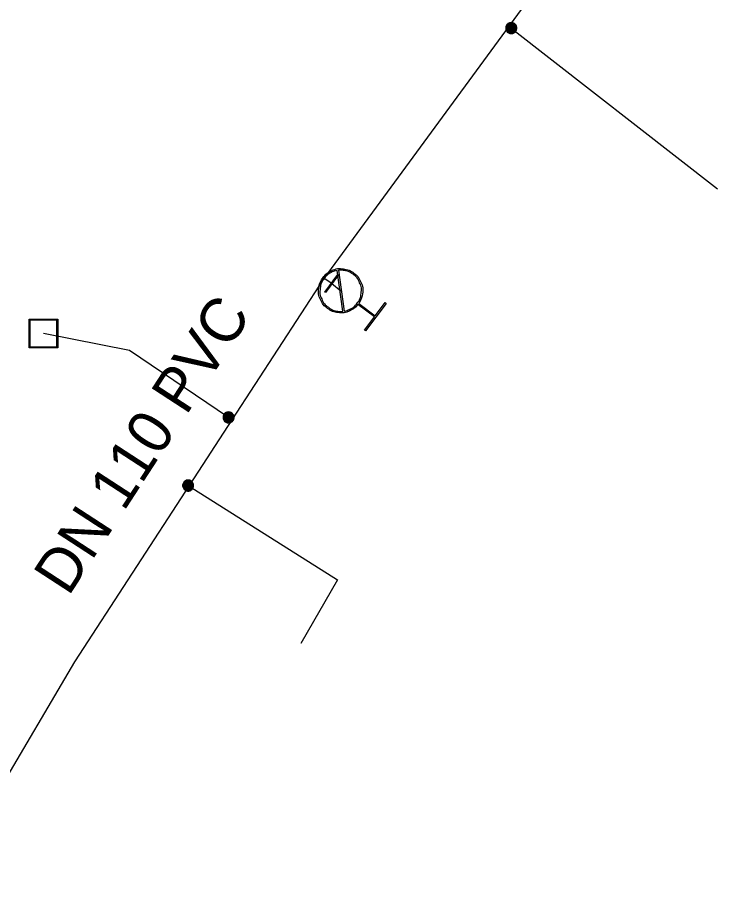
# Model space of a CAD drawing. Extents: x -832382 to -831581, y -1074670 to -1074251.
# Drawn here: x -831800.46 to -831768.62, y -1074542.98 to -1074502.92 of the extents above; entities that cross this region are included whole.
import ezdxf

# ---------------------------------------------------------------- set-up
doc = ezdxf.new("R2010")
doc.units = 0
for name, color, linetype in [('Hyd-odbočka', 7, 'Continuous'), ('Hyd-šoupě', 7, 'Continuous'), ('Hydrant', 7, 'Continuous'), ('Přípojka vodovodu', 7, 'Continuous'), ('Přípojkový uzávěr', 7, 'Continuous'), ('Roz-řad', 7, 'Continuous'), ('Roz-řad-popis základní', 7, 'Continuous'), ('Šachta vodovodní', 7, 'Continuous')]:
    doc.layers.add(name, color=color, linetype=linetype)

msp = doc.modelspace()

# ---------------------------------------------------------------- linework, layer by layer
at = {"layer": 'Hyd-odbočka'}
for q in [(-831786.517, -1074514.779), (-831785.76, -1074515.34)]:
    msp.add_line((-831786.17, -1074515.01), q, dxfattribs=at)
at = {"layer": 'Hyd-šoupě'}
msp.add_lwpolyline([(-831786.479, -1074515.403), (-831785.885, -1074514.599), (-831785.86, -1074514.617), (-831786.454, -1074515.421), (-831786.479, -1074515.403)], dxfattribs=at)
at = {"layer": 'Hydrant'}
for points in [[(-831785.656, -1074516.274), (-831785.926, -1074514.414)], [(-831785.864, -1074514.406), (-831785.596, -1074516.265)], [(-831784.94, -1074515.914), (-831784.189, -1074516.475), (-831783.74, -1074515.874), (-831783.69, -1074515.912), (-831784.626, -1074517.163), (-831784.676, -1074517.126), (-831784.227, -1074516.525), (-831784.978, -1074515.964)]]:
    msp.add_lwpolyline(points, dxfattribs=at)
for points in [[(-831784.978, -1074515.964), (-831785.126, -1074516.148), (-831785.357, -1074516.256), (-831785.603, -1074516.369), (-831785.876, -1074516.334), (-831786.149, -1074516.298), (-831786.359, -1074516.141), (-831786.567, -1074515.985), (-831786.679, -1074515.737), (-831786.791, -1074515.489), (-831786.754, -1074515.219), (-831786.716, -1074514.949), (-831786.561, -1074514.741), (-831786.405, -1074514.533), (-831786.157, -1074514.421), (-831785.909, -1074514.309), (-831785.639, -1074514.346), (-831785.369, -1074514.384), (-831785.161, -1074514.539), (-831784.952, -1074514.696), (-831784.84, -1074514.948), (-831784.728, -1074515.199), (-831784.768, -1074515.467), (-831784.804, -1074515.718), (-831784.94, -1074515.914)], [(-831785.926, -1074514.414), (-831786.031, -1074514.433), (-831786.131, -1074514.48), (-831786.365, -1074514.583), (-831786.511, -1074514.779), (-831786.657, -1074514.974), (-831786.692, -1074515.228), (-831786.726, -1074515.481), (-831786.622, -1074515.713), (-831786.517, -1074515.945), (-831786.321, -1074516.091), (-831786.124, -1074516.238), (-831785.868, -1074516.271), (-831785.759, -1074516.285), (-831785.656, -1074516.274)], [(-831785.596, -1074516.265), (-831785.486, -1074516.245), (-831785.382, -1074516.198), (-831785.151, -1074516.091), (-831785.009, -1074515.901), (-831784.868, -1074515.712), (-831784.83, -1074515.46), (-831784.793, -1074515.207), (-831784.897, -1074514.972), (-831785.002, -1074514.736), (-831785.199, -1074514.589), (-831785.394, -1074514.443), (-831785.647, -1074514.41), (-831785.757, -1074514.394), (-831785.864, -1074514.406)]]:
    msp.add_open_spline(points, degree=3, dxfattribs=at)
at = {"layer": 'Přípojka vodovodu'}
for points in [[(-831778.085, -1074503.291), (-831778, -1074503.39), (-831768.624, -1074510.708)], [(-831790.697, -1074521.21), (-831790.86, -1074521.1), (-831795.371, -1074518.06), (-831799.285, -1074517.283)], [(-831792.611, -1074524.153), (-831792.7, -1074524.2), (-831785.906, -1074528.481), (-831787.57, -1074531.385)]]:
    msp.add_lwpolyline(points, dxfattribs=at)
at = {"layer": 'Přípojkový uzávěr'}
for points in [[(-831778, -1074503.14), (-831777.937, -1074503.14), (-831777.877, -1074503.172), (-831777.818, -1074503.204), (-831777.784, -1074503.265), (-831777.75, -1074503.325), (-831777.75, -1074503.39), (-831777.75, -1074503.455), (-831777.783, -1074503.515), (-831777.816, -1074503.574), (-831777.875, -1074503.607), (-831777.935, -1074503.64), (-831778, -1074503.64), (-831778.065, -1074503.64), (-831778.125, -1074503.607), (-831778.184, -1074503.574), (-831778.217, -1074503.515), (-831778.25, -1074503.455), (-831778.25, -1074503.39), (-831778.25, -1074503.325), (-831778.216, -1074503.265), (-831778.183, -1074503.204), (-831778.123, -1074503.172), (-831778.063, -1074503.14), (-831778, -1074503.14)], [(-831778, -1074503.163), (-831778.057, -1074503.163), (-831778.112, -1074503.193), (-831778.166, -1074503.222), (-831778.196, -1074503.276), (-831778.227, -1074503.331), (-831778.227, -1074503.39), (-831778.227, -1074503.449), (-831778.197, -1074503.503), (-831778.167, -1074503.557), (-831778.113, -1074503.587), (-831778.059, -1074503.617), (-831778, -1074503.617), (-831777.941, -1074503.617), (-831777.887, -1074503.587), (-831777.833, -1074503.557), (-831777.803, -1074503.503), (-831777.773, -1074503.449), (-831777.773, -1074503.39), (-831777.773, -1074503.331), (-831777.804, -1074503.276), (-831777.835, -1074503.222), (-831777.889, -1074503.193), (-831777.943, -1074503.163), (-831778, -1074503.163)], [(-831778, -1074503.181), (-831777.947, -1074503.181), (-831777.897, -1074503.208), (-831777.847, -1074503.234), (-831777.819, -1074503.285), (-831777.791, -1074503.335), (-831777.791, -1074503.39), (-831777.791, -1074503.445), (-831777.818, -1074503.494), (-831777.845, -1074503.544), (-831777.896, -1074503.572), (-831777.946, -1074503.599), (-831778, -1074503.599), (-831778.054, -1074503.599), (-831778.104, -1074503.572), (-831778.155, -1074503.544), (-831778.182, -1074503.494), (-831778.209, -1074503.445), (-831778.209, -1074503.39), (-831778.209, -1074503.335), (-831778.181, -1074503.285), (-831778.153, -1074503.234), (-831778.103, -1074503.208), (-831778.053, -1074503.181), (-831778, -1074503.181)], [(-831778, -1074503.203), (-831778.079, -1074503.203), (-831778.133, -1074503.257), (-831778.188, -1074503.312), (-831778.188, -1074503.39), (-831778.188, -1074503.468), (-831778.133, -1074503.523), (-831778.078, -1074503.578), (-831778, -1074503.578), (-831777.922, -1074503.578), (-831777.867, -1074503.523), (-831777.812, -1074503.468), (-831777.812, -1074503.39), (-831777.812, -1074503.312), (-831777.867, -1074503.257), (-831777.922, -1074503.203), (-831778, -1074503.203)], [(-831778, -1074503.225), (-831777.932, -1074503.225), (-831777.884, -1074503.273), (-831777.836, -1074503.321), (-831777.836, -1074503.39), (-831777.836, -1074503.458), (-831777.884, -1074503.506), (-831777.932, -1074503.554), (-831778, -1074503.554), (-831778.069, -1074503.554), (-831778.117, -1074503.506), (-831778.165, -1074503.458), (-831778.165, -1074503.39), (-831778.165, -1074503.321), (-831778.117, -1074503.273), (-831778.069, -1074503.225), (-831778, -1074503.225)], [(-831778, -1074503.245), (-831778.061, -1074503.245), (-831778.103, -1074503.287), (-831778.145, -1074503.33), (-831778.145, -1074503.39), (-831778.145, -1074503.449), (-831778.103, -1074503.492), (-831778.061, -1074503.534), (-831778, -1074503.534), (-831777.941, -1074503.534), (-831777.898, -1074503.492), (-831777.856, -1074503.449), (-831777.856, -1074503.39), (-831777.856, -1074503.33), (-831777.898, -1074503.287), (-831777.94, -1074503.245), (-831778, -1074503.245)], [(-831778, -1074503.265), (-831777.948, -1074503.265), (-831777.911, -1074503.302), (-831777.875, -1074503.338), (-831777.875, -1074503.39), (-831777.875, -1074503.442), (-831777.912, -1074503.479), (-831777.948, -1074503.515), (-831778, -1074503.515), (-831778.052, -1074503.515), (-831778.088, -1074503.479), (-831778.125, -1074503.442), (-831778.125, -1074503.39), (-831778.125, -1074503.338), (-831778.089, -1074503.302), (-831778.052, -1074503.265), (-831778, -1074503.265)], [(-831778, -1074503.288), (-831778.042, -1074503.288), (-831778.072, -1074503.318), (-831778.102, -1074503.348), (-831778.102, -1074503.39), (-831778.102, -1074503.432), (-831778.072, -1074503.462), (-831778.042, -1074503.491), (-831778, -1074503.491), (-831777.958, -1074503.491), (-831777.928, -1074503.462), (-831777.899, -1074503.432), (-831777.899, -1074503.39), (-831777.899, -1074503.348), (-831777.928, -1074503.318), (-831777.958, -1074503.288), (-831778, -1074503.288)], [(-831778, -1074503.306), (-831777.965, -1074503.306), (-831777.941, -1074503.33), (-831777.916, -1074503.355), (-831777.916, -1074503.39), (-831777.916, -1074503.425), (-831777.941, -1074503.449), (-831777.965, -1074503.474), (-831778, -1074503.474), (-831778.035, -1074503.474), (-831778.06, -1074503.449), (-831778.084, -1074503.425), (-831778.084, -1074503.39), (-831778.084, -1074503.355), (-831778.06, -1074503.33), (-831778.035, -1074503.306), (-831778, -1074503.306)], [(-831778, -1074503.328), (-831778.026, -1074503.328), (-831778.044, -1074503.346), (-831778.062, -1074503.364), (-831778.062, -1074503.39), (-831778.062, -1074503.416), (-831778.044, -1074503.434), (-831778.026, -1074503.453), (-831778, -1074503.453), (-831777.974, -1074503.453), (-831777.956, -1074503.434), (-831777.938, -1074503.416), (-831777.938, -1074503.39), (-831777.938, -1074503.364), (-831777.956, -1074503.346), (-831777.974, -1074503.328), (-831778, -1074503.328)], [(-831778, -1074503.351), (-831777.984, -1074503.351), (-831777.972, -1074503.362), (-831777.961, -1074503.373), (-831777.961, -1074503.39), (-831777.961, -1074503.406), (-831777.972, -1074503.418), (-831777.984, -1074503.429), (-831778, -1074503.429), (-831778.016, -1074503.429), (-831778.028, -1074503.418), (-831778.039, -1074503.406), (-831778.039, -1074503.39), (-831778.039, -1074503.373), (-831778.028, -1074503.362), (-831778.016, -1074503.351), (-831778, -1074503.351)], [(-831778, -1074503.367), (-831778.01, -1074503.367), (-831778.017, -1074503.373), (-831778.024, -1074503.38), (-831778.024, -1074503.39), (-831778.024, -1074503.4), (-831778.017, -1074503.407), (-831778.01, -1074503.413), (-831778, -1074503.413), (-831777.99, -1074503.413), (-831777.984, -1074503.407), (-831777.977, -1074503.4), (-831777.977, -1074503.39), (-831777.977, -1074503.38), (-831777.984, -1074503.373), (-831777.99, -1074503.367), (-831778, -1074503.367)], [(-831790.86, -1074520.85), (-831790.797, -1074520.85), (-831790.737, -1074520.882), (-831790.678, -1074520.914), (-831790.644, -1074520.975), (-831790.61, -1074521.035), (-831790.61, -1074521.1), (-831790.61, -1074521.165), (-831790.643, -1074521.225), (-831790.676, -1074521.284), (-831790.735, -1074521.317), (-831790.795, -1074521.35), (-831790.86, -1074521.35), (-831790.925, -1074521.35), (-831790.985, -1074521.317), (-831791.044, -1074521.284), (-831791.077, -1074521.225), (-831791.11, -1074521.165), (-831791.11, -1074521.1), (-831791.11, -1074521.035), (-831791.076, -1074520.975), (-831791.043, -1074520.914), (-831790.983, -1074520.882), (-831790.923, -1074520.85), (-831790.86, -1074520.85)], [(-831790.86, -1074520.873), (-831790.917, -1074520.873), (-831790.972, -1074520.903), (-831791.026, -1074520.932), (-831791.056, -1074520.986), (-831791.087, -1074521.041), (-831791.087, -1074521.1), (-831791.087, -1074521.159), (-831791.057, -1074521.213), (-831791.027, -1074521.267), (-831790.973, -1074521.297), (-831790.919, -1074521.327), (-831790.86, -1074521.327), (-831790.801, -1074521.327), (-831790.747, -1074521.297), (-831790.693, -1074521.267), (-831790.663, -1074521.213), (-831790.633, -1074521.159), (-831790.633, -1074521.1), (-831790.633, -1074521.041), (-831790.664, -1074520.986), (-831790.695, -1074520.932), (-831790.749, -1074520.903), (-831790.803, -1074520.873), (-831790.86, -1074520.873)], [(-831790.86, -1074520.891), (-831790.807, -1074520.891), (-831790.757, -1074520.918), (-831790.707, -1074520.944), (-831790.679, -1074520.995), (-831790.651, -1074521.045), (-831790.651, -1074521.1), (-831790.651, -1074521.155), (-831790.678, -1074521.204), (-831790.705, -1074521.254), (-831790.756, -1074521.282), (-831790.806, -1074521.309), (-831790.86, -1074521.309), (-831790.914, -1074521.309), (-831790.964, -1074521.282), (-831791.015, -1074521.254), (-831791.042, -1074521.204), (-831791.069, -1074521.155), (-831791.069, -1074521.1), (-831791.069, -1074521.045), (-831791.041, -1074520.995), (-831791.013, -1074520.944), (-831790.963, -1074520.918), (-831790.913, -1074520.891), (-831790.86, -1074520.891)], [(-831790.86, -1074520.913), (-831790.939, -1074520.913), (-831790.993, -1074520.967), (-831791.047, -1074521.022), (-831791.047, -1074521.1), (-831791.047, -1074521.178), (-831790.993, -1074521.233), (-831790.938, -1074521.288), (-831790.86, -1074521.288), (-831790.782, -1074521.288), (-831790.727, -1074521.233), (-831790.672, -1074521.178), (-831790.672, -1074521.1), (-831790.672, -1074521.022), (-831790.727, -1074520.967), (-831790.782, -1074520.913), (-831790.86, -1074520.913)], [(-831790.86, -1074520.935), (-831790.792, -1074520.935), (-831790.744, -1074520.983), (-831790.696, -1074521.031), (-831790.696, -1074521.1), (-831790.696, -1074521.168), (-831790.744, -1074521.216), (-831790.792, -1074521.264), (-831790.86, -1074521.264), (-831790.929, -1074521.264), (-831790.977, -1074521.216), (-831791.025, -1074521.168), (-831791.025, -1074521.1), (-831791.025, -1074521.031), (-831790.977, -1074520.983), (-831790.929, -1074520.935), (-831790.86, -1074520.935)], [(-831790.86, -1074520.955), (-831790.921, -1074520.955), (-831790.963, -1074520.997), (-831791.005, -1074521.04), (-831791.005, -1074521.1), (-831791.005, -1074521.159), (-831790.963, -1074521.202), (-831790.921, -1074521.244), (-831790.86, -1074521.244), (-831790.801, -1074521.244), (-831790.758, -1074521.202), (-831790.716, -1074521.159), (-831790.716, -1074521.1), (-831790.716, -1074521.04), (-831790.758, -1074520.997), (-831790.8, -1074520.955), (-831790.86, -1074520.955)], [(-831790.86, -1074520.975), (-831790.808, -1074520.975), (-831790.771, -1074521.012), (-831790.735, -1074521.048), (-831790.735, -1074521.1), (-831790.735, -1074521.152), (-831790.772, -1074521.189), (-831790.808, -1074521.225), (-831790.86, -1074521.225), (-831790.912, -1074521.225), (-831790.948, -1074521.189), (-831790.985, -1074521.152), (-831790.985, -1074521.1), (-831790.985, -1074521.048), (-831790.949, -1074521.012), (-831790.912, -1074520.975), (-831790.86, -1074520.975)], [(-831790.86, -1074520.998), (-831790.902, -1074520.998), (-831790.932, -1074521.028), (-831790.962, -1074521.058), (-831790.962, -1074521.1), (-831790.962, -1074521.142), (-831790.932, -1074521.172), (-831790.902, -1074521.201), (-831790.86, -1074521.201), (-831790.818, -1074521.201), (-831790.788, -1074521.172), (-831790.759, -1074521.142), (-831790.759, -1074521.1), (-831790.759, -1074521.058), (-831790.788, -1074521.028), (-831790.818, -1074520.998), (-831790.86, -1074520.998)], [(-831790.86, -1074521.016), (-831790.825, -1074521.016), (-831790.801, -1074521.04), (-831790.776, -1074521.065), (-831790.776, -1074521.1), (-831790.776, -1074521.135), (-831790.801, -1074521.159), (-831790.825, -1074521.184), (-831790.86, -1074521.184), (-831790.895, -1074521.184), (-831790.92, -1074521.159), (-831790.944, -1074521.135), (-831790.944, -1074521.1), (-831790.944, -1074521.065), (-831790.92, -1074521.04), (-831790.895, -1074521.016), (-831790.86, -1074521.016)], [(-831790.86, -1074521.038), (-831790.886, -1074521.038), (-831790.904, -1074521.056), (-831790.922, -1074521.074), (-831790.922, -1074521.1), (-831790.922, -1074521.126), (-831790.904, -1074521.144), (-831790.886, -1074521.163), (-831790.86, -1074521.163), (-831790.834, -1074521.163), (-831790.816, -1074521.144), (-831790.797, -1074521.126), (-831790.797, -1074521.1), (-831790.797, -1074521.074), (-831790.816, -1074521.056), (-831790.834, -1074521.038), (-831790.86, -1074521.038)], [(-831790.86, -1074521.061), (-831790.844, -1074521.061), (-831790.832, -1074521.072), (-831790.821, -1074521.083), (-831790.821, -1074521.1), (-831790.821, -1074521.116), (-831790.832, -1074521.128), (-831790.844, -1074521.139), (-831790.86, -1074521.139), (-831790.876, -1074521.139), (-831790.888, -1074521.128), (-831790.899, -1074521.116), (-831790.899, -1074521.1), (-831790.899, -1074521.083), (-831790.888, -1074521.072), (-831790.876, -1074521.061), (-831790.86, -1074521.061)], [(-831790.86, -1074521.077), (-831790.87, -1074521.077), (-831790.877, -1074521.083), (-831790.884, -1074521.09), (-831790.884, -1074521.1), (-831790.884, -1074521.11), (-831790.877, -1074521.117), (-831790.87, -1074521.123), (-831790.86, -1074521.123), (-831790.85, -1074521.123), (-831790.844, -1074521.117), (-831790.837, -1074521.11), (-831790.837, -1074521.1), (-831790.837, -1074521.09), (-831790.844, -1074521.083), (-831790.85, -1074521.077), (-831790.86, -1074521.077)], [(-831792.7, -1074523.95), (-831792.637, -1074523.95), (-831792.577, -1074523.982), (-831792.518, -1074524.014), (-831792.484, -1074524.075), (-831792.45, -1074524.135), (-831792.45, -1074524.2), (-831792.45, -1074524.265), (-831792.483, -1074524.325), (-831792.516, -1074524.384), (-831792.575, -1074524.417), (-831792.635, -1074524.45), (-831792.7, -1074524.45), (-831792.765, -1074524.45), (-831792.825, -1074524.417), (-831792.884, -1074524.384), (-831792.917, -1074524.325), (-831792.95, -1074524.265), (-831792.95, -1074524.2), (-831792.95, -1074524.135), (-831792.916, -1074524.075), (-831792.883, -1074524.014), (-831792.823, -1074523.982), (-831792.763, -1074523.95), (-831792.7, -1074523.95)], [(-831792.7, -1074523.973), (-831792.757, -1074523.973), (-831792.812, -1074524.003), (-831792.866, -1074524.032), (-831792.896, -1074524.086), (-831792.927, -1074524.141), (-831792.927, -1074524.2), (-831792.927, -1074524.259), (-831792.897, -1074524.313), (-831792.867, -1074524.367), (-831792.813, -1074524.397), (-831792.759, -1074524.427), (-831792.7, -1074524.427), (-831792.641, -1074524.427), (-831792.587, -1074524.397), (-831792.533, -1074524.367), (-831792.503, -1074524.313), (-831792.473, -1074524.259), (-831792.473, -1074524.2), (-831792.473, -1074524.141), (-831792.504, -1074524.086), (-831792.535, -1074524.032), (-831792.589, -1074524.003), (-831792.643, -1074523.973), (-831792.7, -1074523.973)], [(-831792.7, -1074523.991), (-831792.647, -1074523.991), (-831792.597, -1074524.018), (-831792.547, -1074524.044), (-831792.519, -1074524.095), (-831792.491, -1074524.145), (-831792.491, -1074524.2), (-831792.491, -1074524.255), (-831792.518, -1074524.304), (-831792.545, -1074524.354), (-831792.596, -1074524.382), (-831792.646, -1074524.409), (-831792.7, -1074524.409), (-831792.754, -1074524.409), (-831792.804, -1074524.382), (-831792.855, -1074524.354), (-831792.882, -1074524.304), (-831792.909, -1074524.255), (-831792.909, -1074524.2), (-831792.909, -1074524.145), (-831792.881, -1074524.095), (-831792.853, -1074524.044), (-831792.803, -1074524.018), (-831792.753, -1074523.991), (-831792.7, -1074523.991)], [(-831792.7, -1074524.012), (-831792.779, -1074524.012), (-831792.833, -1074524.067), (-831792.888, -1074524.122), (-831792.888, -1074524.2), (-831792.888, -1074524.278), (-831792.833, -1074524.333), (-831792.778, -1074524.387), (-831792.7, -1074524.387), (-831792.622, -1074524.387), (-831792.567, -1074524.333), (-831792.513, -1074524.278), (-831792.513, -1074524.2), (-831792.513, -1074524.122), (-831792.567, -1074524.067), (-831792.622, -1074524.012), (-831792.7, -1074524.012)], [(-831792.7, -1074524.035), (-831792.632, -1074524.035), (-831792.584, -1074524.083), (-831792.536, -1074524.131), (-831792.536, -1074524.2), (-831792.536, -1074524.268), (-831792.584, -1074524.316), (-831792.632, -1074524.364), (-831792.7, -1074524.364), (-831792.769, -1074524.364), (-831792.817, -1074524.316), (-831792.865, -1074524.268), (-831792.865, -1074524.2), (-831792.865, -1074524.131), (-831792.817, -1074524.083), (-831792.769, -1074524.035), (-831792.7, -1074524.035)], [(-831792.7, -1074524.055), (-831792.761, -1074524.055), (-831792.803, -1074524.097), (-831792.845, -1074524.14), (-831792.845, -1074524.2), (-831792.845, -1074524.259), (-831792.803, -1074524.302), (-831792.761, -1074524.344), (-831792.7, -1074524.344), (-831792.641, -1074524.344), (-831792.598, -1074524.302), (-831792.556, -1074524.259), (-831792.556, -1074524.2), (-831792.556, -1074524.14), (-831792.598, -1074524.097), (-831792.64, -1074524.055), (-831792.7, -1074524.055)], [(-831792.7, -1074524.075), (-831792.648, -1074524.075), (-831792.611, -1074524.112), (-831792.575, -1074524.148), (-831792.575, -1074524.2), (-831792.575, -1074524.252), (-831792.612, -1074524.289), (-831792.648, -1074524.325), (-831792.7, -1074524.325), (-831792.752, -1074524.325), (-831792.788, -1074524.289), (-831792.825, -1074524.252), (-831792.825, -1074524.2), (-831792.825, -1074524.148), (-831792.789, -1074524.112), (-831792.752, -1074524.075), (-831792.7, -1074524.075)], [(-831792.7, -1074524.098), (-831792.742, -1074524.098), (-831792.772, -1074524.128), (-831792.802, -1074524.158), (-831792.802, -1074524.2), (-831792.802, -1074524.242), (-831792.772, -1074524.272), (-831792.742, -1074524.301), (-831792.7, -1074524.301), (-831792.658, -1074524.301), (-831792.628, -1074524.272), (-831792.599, -1074524.242), (-831792.599, -1074524.2), (-831792.599, -1074524.158), (-831792.628, -1074524.128), (-831792.658, -1074524.098), (-831792.7, -1074524.098)], [(-831792.7, -1074524.116), (-831792.665, -1074524.116), (-831792.641, -1074524.14), (-831792.616, -1074524.165), (-831792.616, -1074524.2), (-831792.616, -1074524.235), (-831792.641, -1074524.259), (-831792.665, -1074524.284), (-831792.7, -1074524.284), (-831792.735, -1074524.284), (-831792.76, -1074524.259), (-831792.784, -1074524.235), (-831792.784, -1074524.2), (-831792.784, -1074524.165), (-831792.76, -1074524.14), (-831792.735, -1074524.116), (-831792.7, -1074524.116)], [(-831792.7, -1074524.137), (-831792.726, -1074524.137), (-831792.744, -1074524.156), (-831792.763, -1074524.174), (-831792.763, -1074524.2), (-831792.763, -1074524.226), (-831792.744, -1074524.244), (-831792.726, -1074524.262), (-831792.7, -1074524.262), (-831792.674, -1074524.262), (-831792.656, -1074524.244), (-831792.638, -1074524.226), (-831792.638, -1074524.2), (-831792.638, -1074524.174), (-831792.656, -1074524.156), (-831792.674, -1074524.137), (-831792.7, -1074524.137)], [(-831792.7, -1074524.161), (-831792.684, -1074524.161), (-831792.672, -1074524.172), (-831792.661, -1074524.183), (-831792.661, -1074524.2), (-831792.661, -1074524.216), (-831792.672, -1074524.228), (-831792.684, -1074524.239), (-831792.7, -1074524.239), (-831792.716, -1074524.239), (-831792.728, -1074524.228), (-831792.739, -1074524.216), (-831792.739, -1074524.2), (-831792.739, -1074524.183), (-831792.728, -1074524.172), (-831792.716, -1074524.161), (-831792.7, -1074524.161)], [(-831792.7, -1074524.177), (-831792.71, -1074524.177), (-831792.717, -1074524.183), (-831792.724, -1074524.19), (-831792.724, -1074524.2), (-831792.724, -1074524.21), (-831792.717, -1074524.217), (-831792.71, -1074524.223), (-831792.7, -1074524.223), (-831792.69, -1074524.223), (-831792.684, -1074524.217), (-831792.677, -1074524.21), (-831792.677, -1074524.2), (-831792.677, -1074524.19), (-831792.684, -1074524.183), (-831792.69, -1074524.177), (-831792.7, -1074524.177)]]:
    msp.add_open_spline(points, degree=3, dxfattribs=at)
at = {"layer": 'Roz-řad'}
msp.add_lwpolyline([(-831826.43, -1074593.59), (-831826.17, -1074591.37), (-831825.748, -1074588.84), (-831823.95, -1074578.05), (-831819.17, -1074568.98), (-831812.29, -1074556.71), (-831807.224, -1074548.114), (-831804.784, -1074543.992), (-831801.398, -1074538.225), (-831797.86, -1074532.22), (-831792.611, -1074524.153), (-831790.697, -1074521.21), (-831786.517, -1074514.779), (-831778.085, -1074503.291), (-831772.842, -1074496.164)], dxfattribs=at)
at = {"layer": 'Šachta vodovodní'}
for points in [[(-831798.635, -1074516.633), (-831798.635, -1074517.933), (-831799.935, -1074517.933), (-831799.935, -1074516.633), (-831798.635, -1074516.633)], [(-831799.894, -1074516.674), (-831799.894, -1074517.893), (-831798.676, -1074517.893), (-831798.676, -1074516.674), (-831799.894, -1074516.674)]]:
    msp.add_lwpolyline(points, dxfattribs=at)

# ---------------------------------------------------------------- texts
at = {"layer": 'Roz-řad-popis základní'}
msp.add_text('DN 110 PVC', height=2, rotation=56.9615, dxfattribs=at).set_placement((-831798.146, -1074529.279))

doc.saveas('drawing.dxf')
